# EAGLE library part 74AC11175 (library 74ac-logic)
Quadruple positive edge triggered D-type Flip-Flop
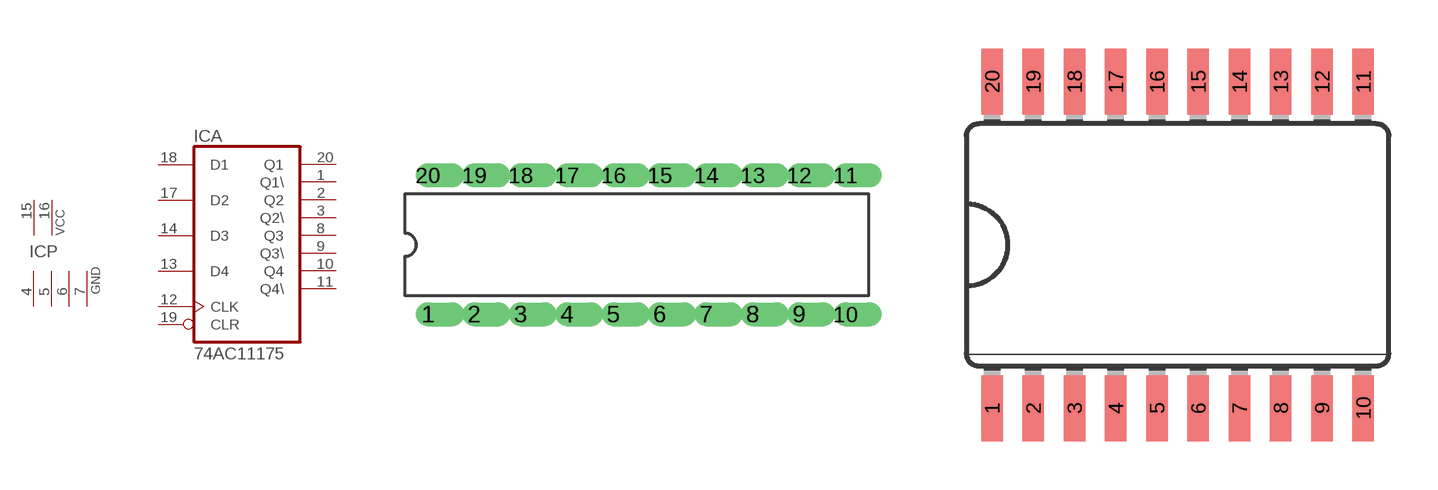
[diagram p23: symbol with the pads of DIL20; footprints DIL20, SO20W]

Designator prefix IC; gates A=7411175 P=2PWR4GND

## 74AC11175  [DIL20]
1  A:Q1\  out
2  A:Q2  out
3  A:Q2\  out
4  P:GND  pwr
5  P:GND  pwr
6  P:GND  pwr
7  P:GND  pwr
8  A:Q3  out
9  A:Q3\  out
10  A:Q4  out
11  A:Q4\  out
12  A:CLK  in
13  A:D4  in
14  A:D3  in
15  P:VCC  pwr
16  P:VCC  pwr
17  A:D2  in
18  A:D1  in
19  A:CLR  in
20  A:Q1  out

## 74AC11175D  [SO20W]
Pads as for DIL20

## Footprint DIL20 (pad centres in mm)
Dual In Line
drill 0.813 offset: 1 -11.43,-3.81; 2 -8.89,-3.81; 3 -6.35,-3.81; 4 -3.81,-3.81; 5 -1.27,-3.81; 6 1.27,-3.81; 7 3.81,-3.81; 8 6.35,-3.81; 9 8.89,-3.81; 10 11.43,-3.81; 11 11.43,3.81; 12 8.89,3.81; 13 6.35,3.81; 14 3.81,3.81; 15 1.27,3.81; 16 -1.27,3.81; 17 -3.81,3.81; 18 -6.35,3.81; 19 -8.89,3.81; 20 -11.43,3.81

## Footprint SO20W (pad centres in mm)
Wide Small Outline package 300 mil
smd 0.66 x 2.032: 1 -5.715,-5.029; 2 -4.445,-5.029; 3 -3.175,-5.029; 4 -1.905,-5.029; 5 -0.635,-5.029; 6 0.635,-5.029; 7 1.905,-5.029; 8 3.175,-5.029; 9 4.445,-5.029; 10 5.715,-5.029; 11 5.715,5.029; 12 4.445,5.029; 13 3.175,5.029; 14 1.905,5.029; 15 0.635,5.029; 16 -0.635,5.029; 17 -1.905,5.029; 18 -3.175,5.029; 19 -4.445,5.029; 20 -5.715,5.029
